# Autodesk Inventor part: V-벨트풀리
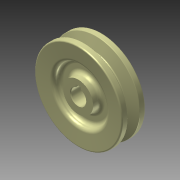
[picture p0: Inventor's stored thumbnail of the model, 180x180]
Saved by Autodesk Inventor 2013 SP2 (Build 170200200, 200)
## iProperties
Created: 2016-08
Part Number: V-벨트풀리
Material: 일반
Document SubType Name: Modeling
Designer: mduedu
Density: 1 g/cm^3
Mass: 44.0848 g
Surface Area: 158.218 cm^2
Volume: 44.0848 cm^3
Author: mduedu
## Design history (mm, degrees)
sketch "스케치1"
  geometry: L1 (0, 9.5)-(0, -9.5); L2 (0, 9.5)-(35, 9.5); L3 (35, 9.5)-(35, 4.825); L4 (35, 4.825)-(26, 2.074); L5 (26, 2.074)-(26, 0); L6 (0, 0)-(26, 0); L7 (0, -9.5)-(35, -9.5); L8 (35, -9.5)-(35, -4.825); L9 (35, -4.825)-(26, -2.074); L10 (26, -2.074)-(26, 0); L11 (32.3, 9.5)-(32.3, -9.5); 3 further points
  constraints: 22 end point, 6 point on line, 4 perpendicular, 3 symmetric about line, 1 coincident, 1 horizontal alignment, 1 midpoint, 1 parallel, 1 vertical
  dimensions: "d0" = 19 distance of L1.start L1.end; "d2" = 70 diameter of L8 L1; "d4" = 6.3 distance between parallel lines of L10 L11; "d5" = 2.7 distance between parallel lines of L11 L8; "d6" = 8 distance of point (32.3, -4) point (32.3, 4); "d7" = 34 deg angle of L9 L4
revolve "회전1" sketch "스케치1" stored, may be unused: angle "d8" = 90 deg
sketch "스케치2"
  geometry: L1 (-2, 0)-(2, 0); L2 (2, 0)-(2, 7.8); L3 (2, 7.8)-(-2, 7.8); L4 (-2, 7.8)-(-2, 0); C1 r 6 at (0, 0); 2 further points
  constraints: 8 end point, 2 coincident, 2 parallel, 1 centre point, 1 horizontal, 1 midpoint, 1 perpendicular
  dimensions: "d9" = 12 diameter of C1; "d11" = 4 distance of L2.end L3.end; "d12" = 7.8 distance of L1.end L2.end
extrude "돌출1" cut sketch "스케치2" stored distance "d13" = 10; taper "d14" = 0 deg
sketch "스케치3"
  geometry: L1 (35, 4.825)-(26, 2.074) reference; L2 (26, 2.074)-(26, -2.074) reference; L3 (0, 0)-(26, 0); L4 (35, 9.5)-(35, 4.825) reference; L5 (-35, 9.5)-(35, 9.5) reference; L6 (35, 9.5)-(21, 8.275); L7 (21, 8.275)-(21, 3); L8 (21, 3)-(12, 3); L9 (12, 3)-(12, 9.5); L10 (0, 9.5)-(0, -9.5); L11 (5.657, -9.5)-(-6, -9.5) reference; L12 (12, 9.5)-(35, 9.5)
  constraints: 14 end point, 3 midpoint, 2 perpendicular, 2 point on line, 1 collinear, 1 horizontal, 1 parallel
  dimensions: "d15" = 3 distance between parallel lines of L3 L8; "d17" = 42 diameter of L7 L10; "d18" = 24 diameter of L9 L10; "d31" = 5 deg angle of L6 L5
revolve "회전2" sketch "스케치3" stored, may be unused: angle "d19" = 90 deg
fillet "모깎기1" dims "d20" = 0.5, "d21" = 1, "d22" = 1
fillet "모깎기2" dims "d23" = 3
fillet "모깎기3" dims "d24" = 3
fillet "모깎기4" dims "d25" = 3
chamfer "모따기1" distance "d26" = 0.5; stored, may be unused: second distance "d27" = 2, angle "d28" = 45 deg
node "솔리드1"
mirror "대칭1"
